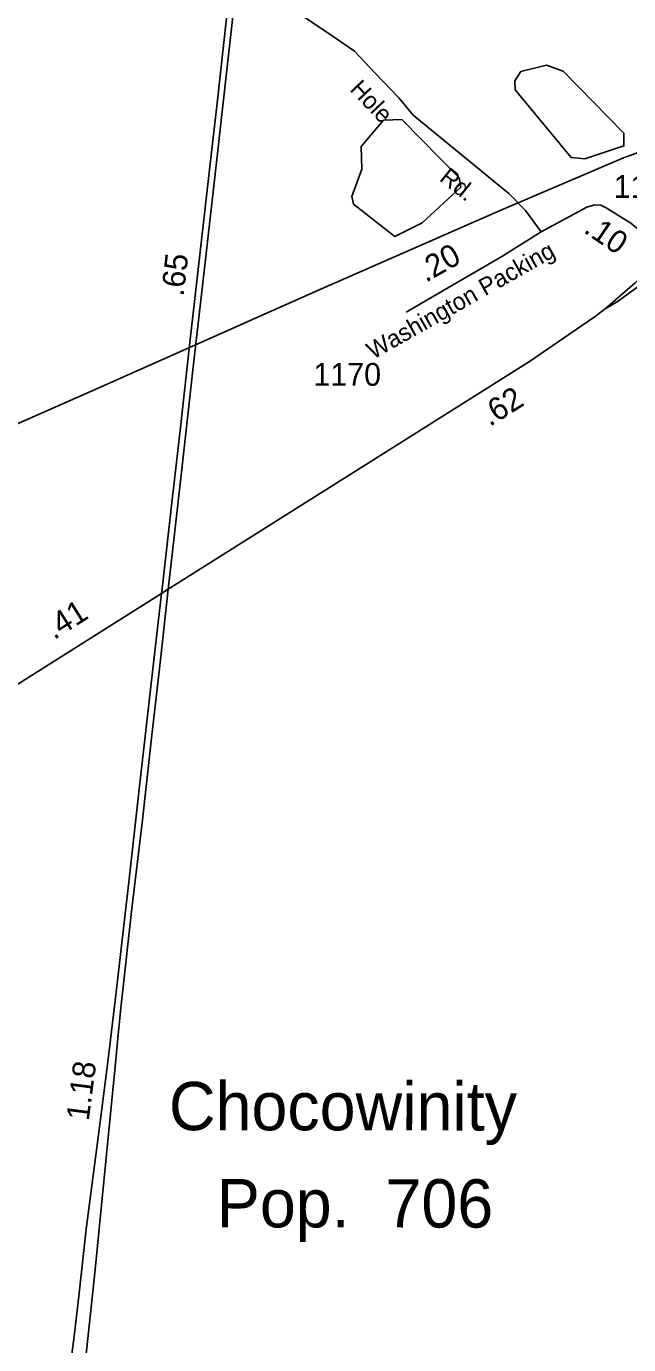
# Model space of a CAD drawing. Extents: x 2532689 to 2764727, y 536648 to 732970.
# Drawn here: x 2569057 to 2572363, y 646803 to 654034 of the extents above; entities that cross this region are included whole.
import ezdxf

# ---------------------------------------------------------------- set-up
doc = ezdxf.new("R2010")
doc.units = 0
for name, color, linetype in [('Exist Civil Demographics City Label', 7, 'Continuous'), ('Exist Hydrographic Pond Under 1500 Sq Ft', 7, 'Continuous'), ('Exist Railroad Mainline', 7, 'Continuous'), ('Exist Road Primary US Attributed', 7, 'Continuous'), ('Exist Road Primary US Divided Attributed', 7, 'Continuous'), ('Exist Road Primary US Mileage Hundredths English Label', 7, 'Continuous'), ('Exist Road Primary US Ramp 1 Lane  Attributed', 7, 'Continuous'), ('Exist Road Secondary Mileage Hundredths English Label', 7, 'Continuous'), ('Exist Road Secondary Type 51 Attributed', 7, 'Continuous'), ('Exist Road Secondary Type 51 Label', 7, 'Continuous'), ('Exist Road Secondary Type 51 Number Label', 7, 'Continuous')]:
    doc.layers.add(name, color=color, linetype=linetype)

msp = doc.modelspace()

# ---------------------------------------------------------------- linework, layer by layer
at = {"layer": 'Exist Hydrographic Pond Under 1500 Sq Ft'}
for points in [[(2572336.1, 653447.7), (2572004.2, 653788.8), (2571912.1, 653821.2), (2571771, 653786), (2571739, 653735.4)], [(2572122.1, 653307.7), (2572047, 653314.5), (2571740.1, 653686.2), (2571739, 653735.4)], [(2570843.2, 653101.6), (2570898.1, 653251.6), (2570895, 653376.3), (2571018.1, 653519.1), (2571068.1, 653521.1)], [(2571229.1, 652956.4), (2571442.1, 653152.1), (2571432.1, 653204.3), (2571118.1, 653523.1), (2571068.1, 653521.1)], [(2572336.1, 653447.7), (2572337.2, 653378.8), (2572122.1, 653307.7)], [(2570843.2, 653101.6), (2570852.2, 653059.3), (2571080.2, 652881.4), (2571229.1, 652956.4)]]:
    msp.add_lwpolyline(points, dxfattribs=at)
at = {"layer": 'Exist Railroad Mainline'}
msp.add_lwpolyline([(2564333.6, 649494.1), (2564516.9, 649751.7), (2564547.7, 649800.5), (2564612.4, 649865.5), (2564845.2, 650034.2), (2565001.7, 650109.4), (2567927.2, 651376.6), (2568400.9, 651587.8), (2569468, 652056.8), (2570647.7, 652581.6), (2571657, 653023.6), (2572335.4, 653312.7), (2572542.2, 653388.7), (2573046.2, 653501.2), (2573203.8, 653536), (2573308.2, 653556.2), (2574260.9, 653760.3), (2574790.3, 653886.8), (2575172.4, 653984.3)], dxfattribs=at)
at = {"layer": 'Exist Road Primary US Attributed'}
for points in [[(2569836.2, 650946.8), (2571819.3, 652195.3), (2572173.5, 652439.1), (2572234.7, 652485.4), (2572399, 652627.8), (2572567.5, 652787)], [(2569799.5, 650923.7), (2569836.2, 650946.8)], [(2566349.3, 648085.5), (2566858.6, 648633.4), (2567107.8, 648884.4), (2567252.6, 649047.2), (2567342.8, 649136.9), (2567395.8, 649189.9), (2567433.1, 649226.9), (2567848.5, 649632.7), (2567888.5, 649671.8), (2567971.1, 649731.2), (2568142.1, 649886.6), (2568231.4, 649936.5), (2569799.5, 650923.7)]]:
    msp.add_lwpolyline(points, dxfattribs=at)
at = {"layer": 'Exist Road Primary US Divided Attributed'}
for points in [[(2570183.9, 654343.2), (2570172.9, 654230.4), (2570138.6, 653929.7), (2570103.9, 653612.6), (2570066, 653281.2), (2570009.5, 652781.3), (2569955.5, 652316.2), (2569902.6, 651833.2), (2569854.3, 651406.4), (2569804.4, 650965.9), (2569799.5, 650923.7)], [(2570219.2, 654326.3), (2570196.4, 654136.3), (2570160.1, 653813.1), (2570106.2, 653336.2), (2570032, 652675), (2569975, 652181.2), (2569908, 651589.5), (2569859.1, 651153.5), (2569836.2, 650946.8)], [(2569836.2, 650946.8), (2569795.2, 650576.7), (2569743.3, 650128.9), (2569691.9, 649665.9), (2569636.9, 649195.6), (2569577.1, 648666.8), (2569560.2, 648501.7), (2569544.9, 648329.3), (2569514.7, 648031.7), (2569482.5, 647696.7), (2569432.6, 647196.8), (2569382.8, 646733.7), (2569351, 646507.5)], [(2569799.5, 650923.7), (2569748.9, 650493.1), (2569674.8, 649833.4), (2569620.8, 649355.5), (2569550.8, 648736.7), (2569504.5, 648353.4), (2569467.7, 648067.5), (2569422.7, 647716.2), (2569385.3, 647436.4), (2569345.2, 647067.9), (2569322.2, 646862.9), (2569292.8, 646635)]]:
    msp.add_lwpolyline(points, dxfattribs=at)
at = {"layer": 'Exist Road Primary US Ramp 1 Lane  Attributed'}
msp.add_lwpolyline([(2572234.7, 652485.4), (2572306.4, 652527), (2572415, 652606.7), (2572494.7, 652673.7), (2572522.5, 652685.3), (2572554.8, 652685.3), (2572605.7, 652670.2), (2572669.2, 652651.8), (2572738.5, 652634.4)], dxfattribs=at)
at = {"layer": 'Exist Road Secondary Type 51 Attributed'}
for points in [[(2571883.3, 652908), (2571796.8, 653025), (2571705.5, 653117.4), (2571180.2, 653548.2), (2571101.4, 653642.8), (2570972.2, 653778.2), (2570858, 653898), (2570741.4, 653978.2), (2570624.5, 654057.4), (2570572.8, 654091.5), (2570231.8, 654315.6), (2570125.3, 654381.1), (2570075.3, 654409.9), (2570028.9, 654439.2), (2569928.5, 654493.8), (2569779.3, 654574), (2569554.6, 654684.4), (2569341.2, 654810.1)], [(2572567.5, 652787), (2572525.9, 652830.9), (2572374.5, 652955.5), (2572239.3, 653038.9), (2572210.5, 653053.9), (2572176.9, 653056.2), (2572134.2, 653043.5), (2571883.3, 652908)], [(2571883.3, 652908), (2571666.8, 652771.9), (2571142.2, 652466.9)]]:
    msp.add_lwpolyline(points, dxfattribs=at)

# ---------------------------------------------------------------- texts
at = {"layer": 'Exist Civil Demographics City Label'}
for s, p in [('Chocowinity', (2569839.7, 647979)), ('Pop.  706', (2570102.4, 647446.3))]:
    msp.add_text(s, height=265, rotation=359.94, dxfattribs=at).set_placement(p)
at = {"layer": 'Exist Road Primary US Mileage Hundredths English Label'}
for s, rotation, p in [('.65', 83.38339, (2569919.8, 652550.2)), ('.62', 32.1931, (2571600.9, 651836.2)), ('.41', 32.1931, (2569208.9, 650666.9)), ('1.18', 82.66063, (2569399.4, 648026.9))]:
    msp.add_text(s, height=125, rotation=rotation, dxfattribs=at).set_placement(p)
at = {"layer": 'Exist Road Secondary Mileage Hundredths English Label'}
for s, rotation, p in [('.10', 325.83782, (2572110.2, 652907.6)), ('.20', 29.45213, (2571250, 652627.3))]:
    msp.add_text(s, height=125, rotation=rotation, dxfattribs=at).set_placement(p)
at = {"layer": 'Exist Road Secondary Type 51 Label'}
for s, rotation, p in [('Hole', 313.62088, (2570827.5, 653685.1)), ('Rd.', 321.44836, (2571319.1, 653192.1)), ('Washington Packing', 29.51213, (2570960.2, 652205.2))]:
    msp.add_text(s, height=95, rotation=rotation, dxfattribs=at).set_placement(p)
at = {"layer": 'Exist Road Secondary Type 51 Number Label'}
for s, p in [('1165', (2572280.6, 653093.4)), ('1170', (2570632.3, 652063.2))]:
    msp.add_text(s, height=125, rotation=359.94, dxfattribs=at).set_placement(p)

doc.saveas('drawing.dxf')
